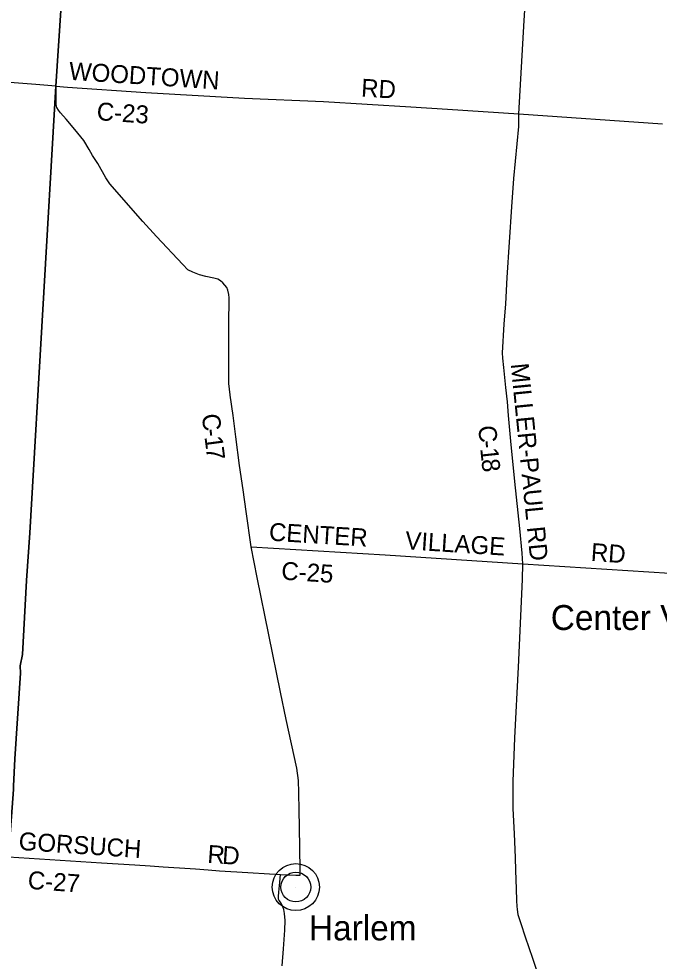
# Model space of a CAD drawing. Extents: x 1674899 to 2057726, y 653888 to 988278.
# Drawn here: x 1868981 to 1879677, y 782644 to 798397 of the extents above; entities that cross this region are included whole.
import ezdxf

# ---------------------------------------------------------------- set-up
doc = ezdxf.new("R2010")
doc.units = 0
for name, color, linetype in [('GM_X_County_Road', 7, 'Continuous'), ('GM_X_County_Road_Text', 7, 'Continuous'), ('GM_X_Township', 7, 'Continuous'), ('GM_X_Unincorporated', 7, 'Continuous'), ('GM_X_Unincorporated_Location', 7, 'Continuous'), ('GM_X_Unincorporated_Text', 7, 'Continuous')]:
    doc.layers.add(name, color=color, linetype=linetype)

msp = doc.modelspace()

# ---------------------------------------------------------------- linework, layer by layer
at = {"layer": 'GM_X_County_Road'}
for points in [[(1877332, 796811), (1877420, 798367), (1877499, 799608), (1877454, 800633), (1877398, 802125), (1877369, 802994)], [(1869596, 797271), (1869264, 797299), (1868606, 797350), (1867949, 797398), (1867262, 797449), (1866957, 797476), (1866512, 797510), (1866160, 797537), (1865389, 797594), (1864651, 797652), (1864490, 797665), (1864412, 797670), (1864397, 797669), (1864380, 797664)], [(1872512, 792112), (1872490, 792299), (1872490, 792441), (1872490, 792557), (1872490, 792879), (1872488, 793281), (1872492, 793732), (1872489, 793791), (1872473, 793859), (1872454, 793904), (1872424, 793943), (1872389, 793984), (1872352, 794016), (1872303, 794045), (1872239, 794060), (1872103, 794090), (1871997, 794120), (1871888, 794161), (1871806, 794204), (1871722, 794290), (1871282, 794757), (1871051, 795010), (1870503, 795638), (1870435, 795737), (1870300, 795980), (1870212, 796114), (1870156, 796211), (1870067, 796366), (1869918, 796549), (1869770, 796721), (1869677, 796824), (1869643, 796870), (1869617, 796918), (1869609, 796940), (1869604, 796966), (1869603, 796991), (1869604, 797040), (1869606, 797200), (1869596, 797271)], [(1869596, 797271), (1869794, 797255), (1871103, 797168), (1872753, 797073), (1874071, 797014), (1875527, 796924), (1876143, 796885), (1877332, 796811)], [(1877401, 789284), (1877390, 789464), (1877348, 789877), (1877267, 790662), (1877198, 791335), (1877163, 791768), (1877144, 791994), (1877118, 792235), (1877082, 792567), (1877064, 792727), (1877062, 792815), (1877091, 793291), (1877116, 793631), (1877141, 794076), (1877219, 795256), (1877251, 795728), (1877331, 796597), (1877332, 796811)], [(1877332, 796811), (1879735, 796644)], [(1873381, 782566), (1873402, 782850), (1873426, 783163), (1873427, 783321), (1873418, 783441), (1873405, 783505), (1873393, 783554), (1873368, 783600), (1873335, 783652), (1873325, 783665), (1873319, 783693), (1873320, 783725), (1873324, 783797), (1873340, 783963), (1873351, 784093), (1873606, 784082), (1873683, 784083), (1873682, 784168), (1873669, 784889), (1873663, 785162), (1873657, 785466), (1873655, 785664), (1873627, 785869), (1873446, 786682), (1873351, 787142), (1872964, 789059), (1872863, 789571), (1872778, 790159), (1872727, 790526), (1872666, 790930), (1872604, 791411), (1872559, 791766), (1872513, 792107), (1872512, 792112)], [(1872863, 789571), (1875101, 789435), (1877401, 789284), (1879855, 789132), (1880616, 789098), (1881806, 789028), (1882295, 788997), (1882567, 788975)], [(1877647, 782454), (1877568, 782686), (1877444, 783047), (1877370, 783269), (1877325, 783417), (1877310, 783511), (1877305, 783560), (1877299, 783658), (1877295, 783854), (1877283, 784157), (1877278, 784375), (1877260, 784771), (1877240, 785195), (1877237, 785645), (1877265, 786378), (1877326, 787557), (1877396, 789022), (1877401, 789284)], [(1868806, 784389), (1870363, 784286), (1870916, 784253), (1871172, 784239), (1871392, 784221), (1871840, 784193), (1871932, 784185), (1872143, 784168), (1872331, 784155), (1872524, 784144), (1872620, 784137), (1873351, 784093)]]:
    msp.add_lwpolyline(points, dxfattribs=at)
at = {"layer": 'GM_X_Township'}
for points in [[(1855314, 804559), (1855512, 804546), (1855904, 804520), (1856177, 804502), (1856300, 804491), (1856579, 804475), (1858107, 804378), (1864561, 803926), (1870008, 803514), (1869596, 797271), (1869163, 789806), (1869111, 789007), (1869039, 787768), (1869000, 787580), (1869008, 787459), (1868914, 786029), (1868892, 785569), (1868890, 785515), (1868806, 784389), (1868751, 783613), (1868734, 783178), (1868439, 777975)], [(1881788, 775208), (1878568, 775400), (1872453, 775754), (1872401, 775756), (1868321, 776001), (1868439, 777975), (1868734, 783178), (1868751, 783613), (1868806, 784389), (1868890, 785515), (1868892, 785569), (1868914, 786029), (1869008, 787459), (1869000, 787580), (1869039, 787768), (1869111, 789007), (1869163, 789806), (1869596, 797271), (1870008, 803514), (1877369, 802994), (1883392, 802588)]]:
    msp.add_lwpolyline(points, dxfattribs=at)
at = {"layer": 'GM_X_Unincorporated'}
for radius in [393, 249]:
    msp.add_circle((1873608, 783883), radius, dxfattribs=at)
at = {"layer": 'GM_X_Unincorporated_Location'}
msp.add_line((1873608, 783883), (1873608, 783883), dxfattribs=at)

# ---------------------------------------------------------------- texts
at = {"layer": 'GM_X_County_Road_Text'}
for s, rotation, p in [('WOODTOWN', 356.2904, (1869810, 797379)), ('RD', 356.5467, (1874693, 797098)), ('C-23', 355.8896, (1870274, 796706)), ('MILLER-PAUL RD', 275.6698, (1877197, 792628)), ('C', 276.5988, (1872036, 791780)), ('-', 277.2566, (1872065, 791531)), ('C', 274.5167, (1876656, 791590)), ('1', 277.3308, (1872081, 791409)), ('-', 275.429, (1876676, 791339)), ('7', 277.3462, (1872104, 791225)), ('1', 275.9484, (1876688, 791214)), ('8', 276.2583, (1876707, 791028)), ('CENTER', 356.4676, (1873153, 789675)), ('VILLAGE', 356.3544, (1875428, 789530)), ('RD', 356.0551, (1878530, 789336)), ('C-25', 356.2316, (1873358, 789024)), ('GORSUCH', 356.1373, (1868970, 784505)), ('R', 356.0198, (1872124, 784289)), ('D', 356.22, (1872371, 784272)), ('C-27', 355.8896, (1869122, 783854))]:
    msp.add_text(s, height=300, rotation=rotation, dxfattribs=at).set_placement(p)
at = {"layer": 'GM_X_Unincorporated_Text'}
for s, p in [('Center Village', (1877867, 788180)), ('Harlem', (1873827, 782992))]:
    msp.add_text(s, height=417, rotation=0, dxfattribs=at).set_placement(p)

doc.saveas('drawing.dxf')
